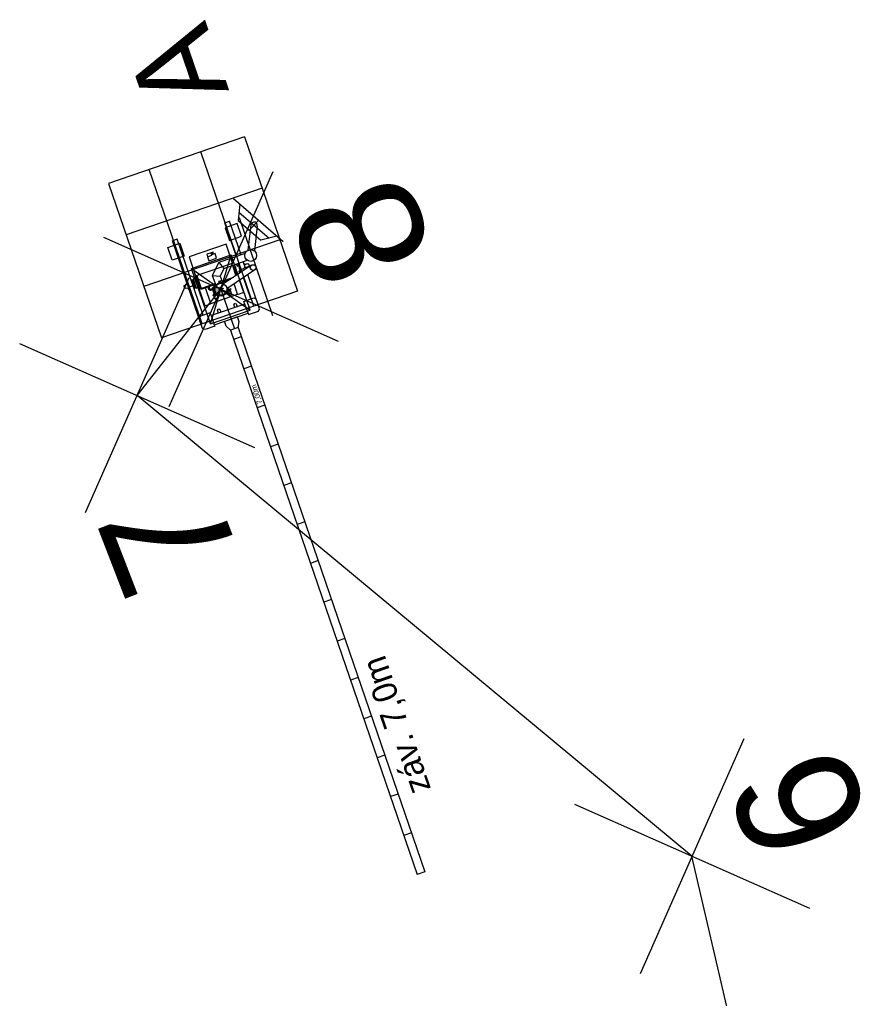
# Model space of a CAD drawing. Extents: x -553584 to -553445, y -1067272 to -1066959.
# Drawn here: x -553515.2 to -553504.92, y -1066980.54 to -1066968.64 of the extents above; entities that cross this region are included whole.
import ezdxf

# ---------------------------------------------------------------- set-up
doc = ezdxf.new("R2010")
doc.units = 0
for name, color, linetype in [('Body', 7, 'Continuous'), ('Default', 7, 'Continuous'), ('Křížky', 7, 'Continuous'), ('Nová kabelizace', 7, 'Continuous'), ('nové prvky ZZ', 7, 'Continuous')]:
    doc.layers.add(name, color=color, linetype=linetype)

# ---------------------------------------------------------------- blocks, each defined once
blk = doc.blocks.new('Křížek')
at = {"layer": 'Křížky'}
for p, q in [((8.839, -8.839), (-8.839, 8.839)), ((8.839, -8.839), (-8.839, 8.839)), ((8.839, -8.839), (-8.839, 8.839)), ((8.839, 8.839), (-8.839, -8.839))]:
    blk.add_line(p, q, dxfattribs=at)

msp = doc.modelspace()

# ---------------------------------------------------------------- linework, layer by layer
at = {"layer": 'Nová kabelizace'}
msp.add_line((-553505.478, -1066985.448), (-553507.017, -1066978.813), dxfattribs=at)
msp.add_lwpolyline([(-553507.017, -1066978.813), (-553513.769, -1066973.209), (-553512.749, -1066971.917)], dxfattribs=at)
at = {"layer": 'nové prvky ZZ'}
for p, q in [((-553512.461, -1066970.063), (-553514.116, -1066970.631)), ((-553512.461, -1066970.063), (-553511.816, -1066971.941)), ((-553512.349, -1066972.124), (-553512.993, -1066970.246)), ((-553512.975, -1066972.339), (-553513.62, -1066970.461)), ((-553514.116, -1066970.631), (-553513.471, -1066972.509)), ((-553512.246, -1066970.689), (-553513.901, -1066971.257)), ((-553512.595, -1066970.814), (-553511.991, -1066971.338)), ((-553512.52, -1066970.88), (-553512.54, -1066971.079)), ((-553512.53, -1066970.979), (-553512.163, -1066971.297)), ((-553512.7, -1066971.109), (-553512.644, -1066971.09)), ((-553512.56, -1066971.518), (-553512.7, -1066971.109)), ((-553512.504, -1066971.499), (-553512.644, -1066971.09)), ((-553512.54, -1066971.079), (-553512.261, -1066971.321)), ((-553512.528, -1066971.045), (-553512.119, -1066972.237)), ((-553512.293, -1066971.076), (-553512.4, -1066971.2)), ((-553512.345, -1066971.146), (-553512.348, -1066971.13)), ((-553512.385, -1066971.135), (-553512.421, -1066971.443)), ((-553512.355, -1066971.139), (-553512.338, -1066971.137)), ((-553512.306, -1066971.145), (-553512.341, -1066971.451)), ((-553512.031, -1066971.315), (-553513.686, -1066971.883)), ((-553513.282, -1066971.308), (-553513.337, -1066971.328)), ((-553512.971, -1066972.394), (-553513.337, -1066971.328)), ((-553512.964, -1066972.234), (-553513.282, -1066971.308)), ((-553512.066, -1066971.273), (-553512.261, -1066971.321)), ((-553512.453, -1066971.481), (-553512.775, -1066971.592)), ((-553513.106, -1066971.666), (-553512.624, -1066971.499)), ((-553513.05, -1066971.646), (-553512.624, -1066971.499)), ((-553512.91, -1066971.521), (-553512.912, -1066971.522)), ((-553512.875, -1066972.337), (-553512.624, -1066971.499)), ((-553512.775, -1066971.592), (-553512.853, -1066971.748)), ((-553512.775, -1066971.592), (-553512.713, -1066971.663)), ((-553512.713, -1066971.663), (-553512.427, -1066971.565)), ((-553512.393, -1066972.17), (-553512.624, -1066971.499)), ((-553512.496, -1066971.704), (-553512.531, -1066971.601)), ((-553512.445, -1066971.67), (-553512.476, -1066971.582)), ((-553512.422, -1066971.607), (-553512.434, -1066971.611)), ((-553512.421, -1066971.611), (-553512.422, -1066971.607)), ((-553512.875, -1066972.337), (-553513.105, -1066971.665)), ((-553513.105, -1066971.665), (-553512.393, -1066972.17)), ((-553512.713, -1066971.663), (-553512.757, -1066971.756)), ((-553512.377, -1066971.624), (-553512.717, -1066971.853)), ((-553512.336, -1066971.681), (-553512.677, -1066971.91)), ((-553512.609, -1066971.628), (-553512.567, -1066971.752)), ((-553512.587, -1066971.659), (-553512.557, -1066971.745)), ((-553512.506, -1066971.675), (-553512.469, -1066971.663)), ((-553512.469, -1066971.663), (-553512.461, -1066971.657)), ((-553512.461, -1066971.657), (-553512.454, -1066971.644)), ((-553512.411, -1066971.64), (-553512.423, -1066971.644)), ((-553512.414, -1066971.609), (-553512.421, -1066971.611)), ((-553512.414, -1066971.609), (-553512.405, -1066971.633)), ((-553512.405, -1066971.633), (-553512.412, -1066971.636)), ((-553512.412, -1066971.636), (-553512.411, -1066971.64)), ((-553513.079, -1066971.816), (-553513.058, -1066971.878)), ((-553513.056, -1066971.755), (-553513.007, -1066971.899)), ((-553513.043, -1066971.751), (-553512.993, -1066971.897)), ((-553512.853, -1066971.748), (-553512.811, -1066971.868)), ((-553512.853, -1066971.748), (-553512.757, -1066971.756)), ((-553512.8, -1066971.856), (-553512.763, -1066971.83)), ((-553512.769, -1066971.848), (-553512.757, -1066971.84)), ((-553512.759, -1066971.82), (-553512.743, -1066971.808)), ((-553512.757, -1066971.756), (-553512.734, -1066971.823)), ((-553512.73, -1066971.829), (-553512.746, -1066971.84)), ((-553512.743, -1066971.808), (-553512.73, -1066971.829)), ((-553512.736, -1066971.818), (-553512.591, -1066971.768)), ((-553512.731, -1066971.828), (-553512.628, -1066971.793)), ((-553512.731, -1066971.83), (-553512.725, -1066971.849)), ((-553512.557, -1066971.744), (-553512.552, -1066971.733)), ((-553512.47, -1066971.957), (-553512.522, -1066971.806)), ((-553512.383, -1066972.035), (-553512.472, -1066971.773)), ((-553512.278, -1066972.156), (-553512.422, -1066971.738)), ((-553511.816, -1066971.941), (-553513.471, -1066972.509)), ((-553513.201, -1066971.879), (-553513.194, -1066971.877)), ((-553513.201, -1066971.879), (-553513.192, -1066971.903)), ((-553513.195, -1066971.873), (-553513.183, -1066971.869)), ((-553513.194, -1066971.877), (-553513.195, -1066971.873)), ((-553513.192, -1066971.903), (-553513.185, -1066971.901)), ((-553513.185, -1066971.901), (-553513.184, -1066971.905)), ((-553513.184, -1066971.905), (-553513.172, -1066971.901)), ((-553513.134, -1066971.888), (-553513.147, -1066971.882)), ((-553513.124, -1066971.888), (-553513.134, -1066971.888)), ((-553513.087, -1066971.875), (-553513.124, -1066971.888)), ((-553513.021, -1066971.894), (-553512.944, -1066972.12)), ((-553513.007, -1066971.899), (-553512.995, -1066971.912)), ((-553512.995, -1066971.912), (-553512.977, -1066971.913)), ((-553512.993, -1066971.897), (-553512.98, -1066971.902)), ((-553512.98, -1066971.902), (-553512.819, -1066971.846)), ((-553512.977, -1066971.913), (-553512.815, -1066971.857)), ((-553512.871, -1066972.089), (-553512.936, -1066971.899)), ((-553512.907, -1066971.888), (-553512.898, -1066971.914)), ((-553512.898, -1066971.914), (-553512.891, -1066971.922)), ((-553512.895, -1066971.884), (-553512.885, -1066971.916)), ((-553512.891, -1066971.922), (-553512.882, -1066971.927)), ((-553512.885, -1066971.916), (-553512.876, -1066971.916)), ((-553512.882, -1066971.927), (-553512.873, -1066971.927)), ((-553512.876, -1066971.916), (-553512.85, -1066971.907)), ((-553512.873, -1066971.927), (-553512.84, -1066971.916)), ((-553512.851, -1066971.92), (-553512.83, -1066971.981)), ((-553512.842, -1066971.911), (-553512.819, -1066971.977)), ((-553512.717, -1066971.906), (-553512.782, -1066971.929)), ((-553512.76, -1066971.885), (-553512.738, -1066971.95)), ((-553512.745, -1066971.916), (-553512.754, -1066971.919)), ((-553512.748, -1066971.922), (-553512.751, -1066971.913)), ((-553512.749, -1066971.917), (-553512.585, -1066972.397)), ((-553512.71, -1066971.986), (-553512.674, -1066971.964)), ((-553512.693, -1066971.963), (-553512.681, -1066971.955)), ((-553512.658, -1066971.931), (-553512.677, -1066971.944)), ((-553512.673, -1066971.908), (-553512.668, -1066971.925)), ((-553512.664, -1066971.964), (-553512.645, -1066971.951)), ((-553512.663, -1066971.901), (-553512.656, -1066971.921)), ((-553512.645, -1066971.951), (-553512.658, -1066971.931)), ((-553512.546, -1066971.978), (-553512.589, -1066971.851)), ((-553512.47, -1066971.957), (-553512.539, -1066971.981)), ((-553512.871, -1066972.089), (-553512.546, -1066971.978)), ((-553512.541, -1066971.976), (-553512.546, -1066971.978)), ((-553512.539, -1066971.981), (-553512.541, -1066971.976)), ((-553512.468, -1066972.064), (-553512.349, -1066972.023)), ((-553512.456, -1066972.097), (-553512.468, -1066972.064)), ((-553512.349, -1066972.023), (-553512.319, -1066972.037)), ((-553512.944, -1066972.12), (-553512.874, -1066972.096)), ((-553512.876, -1066972.091), (-553512.871, -1066972.089)), ((-553512.874, -1066972.096), (-553512.876, -1066972.091)), ((-553512.875, -1066972.337), (-553512.393, -1066972.17)), ((-553512.412, -1066972.226), (-553512.293, -1066972.185)), ((-553512.293, -1066972.185), (-553512.278, -1066972.156)), ((-553512.998, -1066972.246), (-553513.012, -1066972.274)), ((-553512.879, -1066972.205), (-553512.998, -1066972.246)), ((-553512.867, -1066972.238), (-553512.879, -1066972.205)), ((-553512.548, -1066972.254), (-553512.705, -1066972.308)), ((-553512.418, -1066972.209), (-553512.412, -1066972.226)), ((-553512.942, -1066972.408), (-553512.971, -1066972.394)), ((-553512.823, -1066972.367), (-553512.942, -1066972.408)), ((-553512.829, -1066972.35), (-553512.823, -1066972.367)), ((-553512.538, -1066972.381), (-553512.632, -1066972.413)), ((-553512.632, -1066972.413), (-553510.36, -1066979.034)), ((-553512.538, -1066972.381), (-553510.266, -1066979.002)), ((-553512.593, -1066972.525), (-553512.499, -1066972.493)), ((-553512.375, -1066972.854), (-553512.469, -1066972.886)), ((-553512.213, -1066973.327), (-553512.307, -1066973.359)), ((-553512.051, -1066973.8), (-553512.145, -1066973.832)), ((-553511.889, -1066974.273), (-553511.983, -1066974.305)), ((-553511.726, -1066974.746), (-553511.82, -1066974.778)), ((-553511.564, -1066975.218), (-553511.658, -1066975.251)), ((-553511.402, -1066975.691), (-553511.496, -1066975.724)), ((-553511.239, -1066976.164), (-553511.333, -1066976.197)), ((-553511.077, -1066976.637), (-553511.171, -1066976.67)), ((-553510.915, -1066977.11), (-553511.009, -1066977.142)), ((-553510.753, -1066977.583), (-553510.847, -1066977.615)), ((-553510.59, -1066978.056), (-553510.684, -1066978.088)), ((-553510.428, -1066978.529), (-553510.522, -1066978.561)), ((-553510.266, -1066979.002), (-553510.36, -1066979.034))]:
    msp.add_line(p, q, dxfattribs=at)
for points in [[(-553512.696, -1066971.168), (-553512.643, -1066971.323), (-553512.497, -1066971.273), (-553512.55, -1066971.118)], [(-553513.248, -1066971.357), (-553513.195, -1066971.513), (-553513.341, -1066971.563), (-553513.395, -1066971.408)], [(-553513.136, -1066971.523), (-553513.056, -1066971.755), (-553512.606, -1066971.601), (-553512.686, -1066971.369)], [(-553513.111, -1066971.805), (-553513.076, -1066971.908), (-553513.063, -1066971.903), (-553513.098, -1066971.801)], [(-553513.069, -1066971.77), (-553513.053, -1066971.819), (-553513.036, -1066971.813), (-553513.053, -1066971.764)], [(-553512.848, -1066971.904), (-553512.851, -1066971.896), (-553512.833, -1066971.89), (-553512.83, -1066971.898)], [(-553512.811, -1066972.035), (-553512.806, -1066972.05), (-553512.784, -1066972.043), (-553512.789, -1066972.027)], [(-553512.649, -1066971.979), (-553512.644, -1066971.994), (-553512.621, -1066971.987), (-553512.627, -1066971.972)], [(-553512.867, -1066972.238), (-553512.829, -1066972.35), (-553512.418, -1066972.209), (-553512.456, -1066972.097)]]:
    msp.add_lwpolyline(points, close=True, dxfattribs=at)
for points in [[(-553512.869, -1066971.473), (-553512.92, -1066971.491), (-553512.91, -1066971.521), (-553512.858, -1066971.503), (-553512.865, -1066971.484)], [(-553512.912, -1066971.522), (-553512.896, -1066971.57), (-553512.802, -1066971.537), (-553512.82, -1066971.483), (-553512.86, -1066971.497)], [(-553512.865, -1066971.484), (-553512.838, -1066971.475), (-553512.841, -1066971.464), (-553512.869, -1066971.473)], [(-553512.506, -1066971.711), (-553512.54, -1066971.609), (-553512.53, -1066971.606), (-553512.496, -1066971.704)], [(-553512.44, -1066971.667), (-553512.446, -1066971.669), (-553512.467, -1066971.606), (-553512.458, -1066971.602), (-553512.454, -1066971.614)], [(-553512.454, -1066971.614), (-553512.435, -1066971.607), (-553512.434, -1066971.611)], [(-553512.582, -1066971.618), (-553512.57, -1066971.653), (-553512.587, -1066971.659), (-553512.599, -1066971.624)], [(-553512.526, -1066971.724), (-553512.552, -1066971.733), (-553512.579, -1066971.656)], [(-553512.559, -1066971.61), (-553512.551, -1066971.635)], [(-553512.551, -1066971.635), (-553512.534, -1066971.629), (-553512.512, -1066971.691), (-553512.53, -1066971.697)], [(-553512.53, -1066971.697), (-553512.521, -1066971.721)], [(-553512.423, -1066971.644), (-553512.421, -1066971.648), (-553512.44, -1066971.654)], [(-553512.44, -1066971.654), (-553512.436, -1066971.665)], [(-553513.152, -1066971.899), (-553513.148, -1066971.91), (-553513.139, -1066971.907), (-553513.16, -1066971.843), (-553513.17, -1066971.847), (-553513.166, -1066971.858)], [(-553513.079, -1066971.816), (-553513.091, -1066971.82), (-553513.07, -1066971.882), (-553513.058, -1066971.878)], [(-553513.065, -1066971.783), (-553513.088, -1066971.791), (-553513.079, -1066971.816)], [(-553513.058, -1066971.878), (-553513.049, -1066971.904), (-553513.017, -1066971.893), (-553513.043, -1066971.815)], [(-553512.754, -1066971.845), (-553512.772, -1066971.818), (-553512.764, -1066971.813), (-553512.743, -1066971.845)], [(-553513.166, -1066971.858), (-553513.185, -1066971.864), (-553513.183, -1066971.869)], [(-553513.172, -1066971.901), (-553513.171, -1066971.905), (-553513.152, -1066971.899)], [(-553512.827, -1066971.9), (-553512.828, -1066971.897), (-553512.853, -1066971.906), (-553512.85, -1066971.914), (-553512.828, -1066971.906)], [(-553512.684, -1066971.949), (-553512.666, -1066971.977), (-553512.659, -1066971.971), (-553512.68, -1066971.939)], [(-553512.68, -1066971.94), (-553512.662, -1066971.934)], [(-553512.658, -1066971.932), (-553512.625, -1066971.921), (-553512.628, -1066971.911), (-553512.678, -1066971.928)], [(-553512.66, -1066971.973), (-553512.657, -1066971.982), (-553512.619, -1066971.969), (-553512.634, -1066971.924)], [(-553512.806, -1066971.973), (-553512.846, -1066971.986), (-553512.843, -1066971.995), (-553512.799, -1066971.98), (-553512.799, -1066971.98)], [(-553512.798, -1066971.98), (-553512.835, -1066971.993), (-553512.82, -1066972.038), (-553512.781, -1066972.025), (-553512.796, -1066971.982)], [(-553512.766, -1066972.163), (-553512.761, -1066972.161), (-553512.749, -1066972.197), (-553512.776, -1066972.207), (-553512.789, -1066972.171), (-553512.784, -1066972.169)], [(-553512.784, -1066972.169), (-553512.787, -1066972.161), (-553512.769, -1066972.155), (-553512.766, -1066972.163)], [(-553512.567, -1066972.095), (-553512.562, -1066972.093), (-553512.55, -1066972.129), (-553512.578, -1066972.139), (-553512.59, -1066972.103), (-553512.585, -1066972.101)], [(-553512.585, -1066972.101), (-553512.588, -1066972.093), (-553512.57, -1066972.087), (-553512.567, -1066972.095)], [(-553512.632, -1066972.413), (-553512.683, -1066972.367), (-553512.703, -1066972.307)], [(-553512.538, -1066972.381), (-553512.526, -1066972.313), (-553512.546, -1066972.253)]]:
    msp.add_lwpolyline(points, dxfattribs=at)
for centre, radius in [((-553512.347, -1066971.138), 0.00856), ((-553512.386, -1066971.506), 0.0716), ((-553512.356, -1066971.653), 0.0347), ((-553512.749, -1066971.917), 0.0725)]:
    msp.add_circle(centre, radius, dxfattribs=at)
for centre, radius, start, end in [((-553512.345, -1066971.14), 0.0399, 353.2567, 174.9637), ((-553512.749, -1066971.917), 0.0795, 129.387, 299.921)]:
    msp.add_arc(centre, radius, start, end, dxfattribs=at)

# ---------------------------------------------------------------- block references
at = {"layer": 'Body', "xscale": 0.12500000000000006, "yscale": 0.125, "rotation": 111.13806774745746}
for p in [(-553512.749, -1066971.917), (-553513.769, -1066973.209), (-553507.017, -1066978.813)]:
    msp.add_blockref('Křížek', p, dxfattribs=at)

# ---------------------------------------------------------------- texts
at = {"layer": 'Default'}
for s, p in [('8', (-553510.138, -1066971.484)), ('7', (-553512.478, -1066975.236)), ('6', (-553504.812, -1066978.436))]:
    msp.add_text(s, height=1.5, rotation=111.1381, dxfattribs=at).set_placement(p)
at = {"layer": 'nové prvky ZZ'}
for s, height, rotation, p in [('A', 1.025, 108.8917, (-553512.647, -1066969.499)), ('265', 0.025, 108.9398, (-553512.773, -1066971.948)), ('7,00m', 0.0646, 108.9398, (-553512.243, -1066973.303)), ('záv. 7,0m', 0.3, 109.138, (-553510.19, -1066977.993))]:
    msp.add_text(s, height=height, rotation=rotation, dxfattribs=at).set_placement(p)

doc.saveas('drawing.dxf')
